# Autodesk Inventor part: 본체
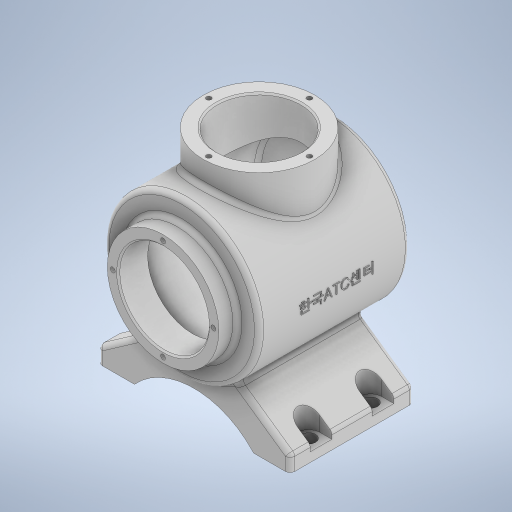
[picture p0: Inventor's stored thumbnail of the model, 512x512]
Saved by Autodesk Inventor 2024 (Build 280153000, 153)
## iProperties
Created: 2023-08
Part Number: 본체
Material: 일반
Document SubType Name: Modeling
Designer: Owner
Density: 1 g/cm^3
Appearance: 기본값
Author: Owner
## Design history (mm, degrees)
sketch "스케치2"
  geometry: L1 (0, 0)-(0, -120); L2 (36, 0)-(36, -12); L3 (36, -12)-(50, -12); L4 (50, -12)-(50, -108.336); L5 (43, -103.887)-(43, -19); L6 (43, -19)-(29, -19); L7 (29, -19)-(29, 0); L8 (29, 0)-(36, 0); A1 r 113 centre (0, -7) between (0, -120) and (50, -108.336); A2 r 106 centre (0, -7) between (0, -113) and (43, -103.887)
  constraints: 16 end point, 4 perpendicular, 4 point on circle, 2 centre point, 2 vertical, 1 horizontal, 1 horizontal alignment, 1 point on line, 1 vertical alignment, 2 other
  dimensions: "d9" = 120 distance of L1.start L1.end; "d10" = 113 radius of A1; "d11" = 72 diameter of L2 L1; "d12" = 100 diameter of L4 L1; "d13" = 108 distance from line of L1.end L3; "d14" = 7 distance between parallel lines of L4 L5; "d15" = 7 radial gap between concentric circles of A1 A2
revolve "회전1" sketch "스케치2" stored, may be unused: angle "d16" = 90 deg
node "작업 평면1"
sketch "스케치3"
  geometry: L1 (-36, 0)-(36, 0) reference; C1 r 36 at (0, -62); 2 further points
  constraints: 1 centre point, 1 midpoint, 1 vertical alignment
  dimensions: "d18" = 62 distance from line of C1.centre L1; "d19" = 72 diameter of C1
extrude "돌출1" join sketch "스케치3" stored distance "d20" = 10; taper "d21" = 0 deg
sketch "스케치4"
  geometry: C1 r 36 at (0, 0) reference; 2 further points
  constraints: 1 coincident
hole "구멍1" sketch "스케치4" at (0, 0) diameter "d22" = 54; stored, may be unused: countersink angle "d26" = 90 deg, drill point angle "d28" = 0 deg; dims "d23" = 8, "d24" = 4, "d25" = 2, "d27" = 40
sketch "스케치5"
  geometry: C1 r 27 at (0, 0) reference; 2 further points
  constraints: 1 horizontal alignment
  dimensions: "d29" = 32.5 distance of C1.centre point (-32.5, 0)
hole "구멍2" sketch "스케치5" at (-32.5, 0) diameter "d30" = 3.242; stored, may be unused: countersink angle "d34" = 90 deg, drill point angle "d36" = 118 deg; dims "d31" = 8, "d32" = 4, "d33" = 2, "d35" = 10
node "작업 평면2"
sketch "스케치6"
  geometry: L1 (38.5, -77)-(62, -77); L2 (62, -77)-(62, -67); L3 (62, -67)-(26.694, -42.278); L4 (0, 0)-(0, -108.924); L5 (-62, -67)-(-26.694, -42.278); L6 (-62, -77)-(-62, -67); L7 (-38.5, -77)-(-62, -77); A1 r 52.096 centre (0, -112.096) between (38.5, -77) and (-38.5, -77); A2 r 50 centre (0, 0) between (26.694, -42.278) and (-26.694, -42.278) reference; 3 further points
  constraints: 14 end point, 4 symmetric about line, 3 point on circle, 1 centre point, 1 horizontal, 1 perpendicular, 1 vertical, 2 other
  dimensions: "d41" = 17 distance from line of L1 point (0, -60); "d42" = 77 distance of L7.start L1.start; "d43" = 10 distance of L1.end L2.end; "d44" = 55 deg angle of L2 L3; "d45" = 77 distance from line of L1 point (0, 0); "d46" = 124 distance between parallel lines of L6 L2
extrude "돌출2" join sketch "스케치6" distance "d47" = 80; taper "d48" = 0 deg
sketch "스케치7"
  geometry: L1 (23.5, 0)-(23.5, -80) reference; L2 (0, 0)-(23.5, 0) reference; 2 further points
  dimensions: "d49" = 8 distance from line of L1 point (15.5, -20); "d50" = 20 distance from line of L2 point (15.5, -20)
hole "구멍3" sketch "스케치7" at (15.5, -20) diameter "d51" = 9; stored, may be unused: countersink angle "d55" = 90 deg, drill point angle "d57" = 0 deg; dims "d52" = 8, "d53" = 4, "d54" = 2, "d56" = 26
node "작업 평면3"
sketch "스케치8"
  geometry: L1 (15.5, -20)-(31.095, -20); L2 (15.5, -27)-(31.095, -27); L3 (31.095, -13)-(15.5, -13); C1 r 4.5 at (15.5, -20) reference; A1 r 7 centre (15.5, -20) between (15.5, -13) and (15.5, -27); A2 r 7 centre (31.095, -20) between (31.095, -27) and (31.095, -13); 2 further points
  constraints: 8 end point, 4 point on circle, 4 tangent, 2 centre point, 1 horizontal, 1 midpoint, 1 parallel
  dimensions: "d59" = 14 distance between parallel lines of L2 L3; "d60" = 15.5952 distance of L1.start L1.end
extrude "돌출3" cut sketch "스케치8" distance "d61" = 22.5; taper "d62" = 0 deg
node "작업 평면5"
sketch "스케치9"
  geometry: C1 r 29 at (0, 0) reference; 2 further points
  constraints: 1 vertical alignment
  dimensions: "d64" = 32.5 distance of point (0, 0) point (0, 32.5)
hole "구멍4" sketch "스케치9" at (0, 32.5) diameter "d65" = 3.242; stored, may be unused: countersink angle "d69" = 90 deg, drill point angle "d71" = 118 deg; dims "d66" = 8, "d67" = 4, "d68" = 2, "d70" = 10
fillet "모깎기1" dims "d75" = 3
fillet "모깎기2" dims "d76" = 3
fillet "모깎기3" dims "d77" = 3
fillet "모깎기4" dims "d78" = 3
fillet "모깎기5" dims "d79" = 3
chamfer "모따기1" distance "d80" = 1; stored, may be unused: second distance "d81" = 2, angle "d82" = 45 deg
node "작업 평면8"
sketch "스케치10"
  geometry: L1 (-36, 60.168)-(36, 60.168) reference; 2 further points
  constraints: 1 vertical alignment, 1 other
  dimensions: "d83" = 62 distance from line of L1 point (0, -1.832)
feature "엠보싱1" sketch "스케치10" dims "d84" = 0.5, "d85" = 0
node "솔리드1"
pattern_circular "원형 패턴1" dims angle "d38" = 360 deg
mirror "미러1"
mirror "미러2"
pattern_circular "원형 패턴2" dims angle "d73" = 360 deg
node "작업 평면4"
node "작업 평면6"
node "작업 평면7"
feature "A9D066F2-1C7D-4E18-AEED-F7BC21143FA4" dims "d22" = 54, "d23" = 8, "d24" = 4, "d25" = 2, "d26" = 90 deg, "d27" = 40, "d28" = 0
other parameters: "d17" = 65, "d58" = -6
